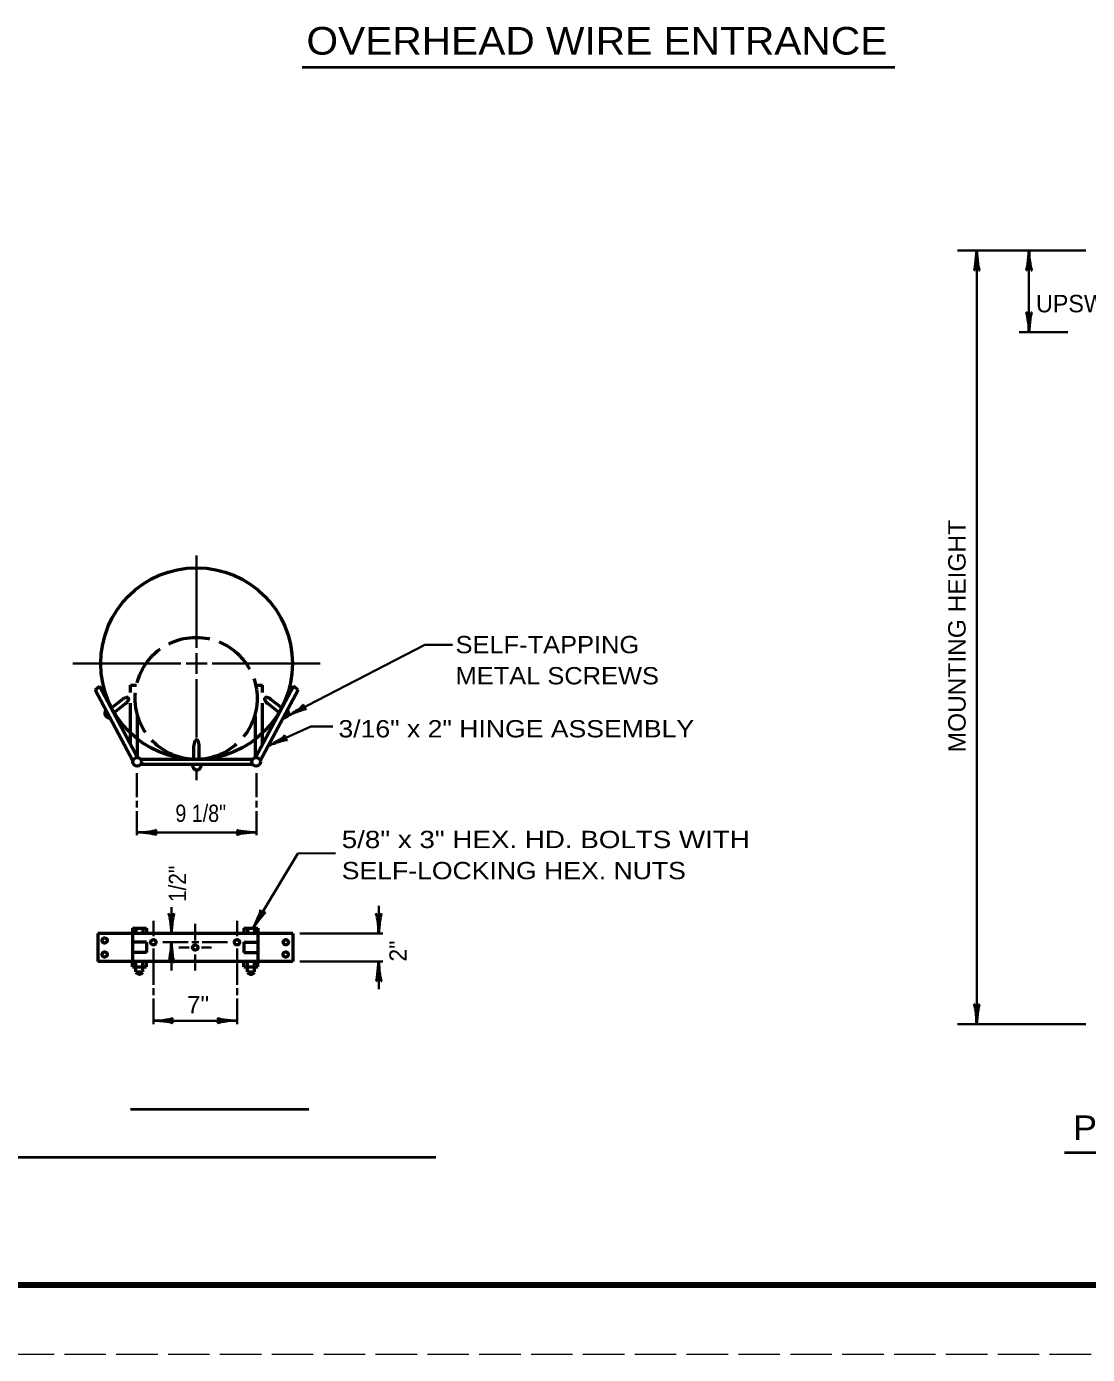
# Model space of a CAD drawing. Extents: x -1 to 679, y -228 to 440.
# Drawn here: x 202.5 to 356, y 0.2 to 192.2 of the extents above; entities that cross this region are included whole.
import ezdxf

# ---------------------------------------------------------------- set-up
doc = ezdxf.new("R2010")
doc.units = 0
doc.linetypes.add('LONG_DASHED', pattern=[7.5, 6, -1.5])
doc.layers.add('1', color=7, linetype='Continuous', lineweight=35)
doc.layers.add('61', color=7, linetype='Continuous', lineweight=35)

msp = doc.modelspace()

# ---------------------------------------------------------------- linework, layer by layer
at = {"layer": '1', "lineweight": 40}
for p, q in [((242.425, 186.371), (328.129, 186.371)), ((217.592, 35.681), (243.388, 35.681)), ((352.69, 29.414), (407.27, 29.414)), ((198.293, 28.717), (261.764, 28.717))]:
    msp.add_line(p, q, dxfattribs=at)
at = {"layer": '1'}
for p, q in [((355.77, 159.854), (337.171, 159.854)), ((339.971, 159.854), (339.971, 47.974)), ((347.53, 148.054), (347.53, 159.854)), ((353.171, 148.054), (346.13, 148.054)), ((227.134, 115.748), (227.134, 102.388)), ((240.289, 92.534), (260.144, 102.807)), ((260.144, 102.807), (264.151, 102.824)), ((209.234, 100.127), (224.874, 100.127)), ((225.614, 100.127), (228.654, 100.127)), ((227.134, 101.627), (227.134, 98.608)), ((229.394, 100.127), (245.014, 100.127)), ((227.134, 97.847), (227.134, 89.407)), ((218.511, 84.285), (218.511, 80.785)), ((227.134, 84.487), (227.134, 83.227)), ((235.796, 84.285), (235.796, 80.785)), ((218.511, 80.285), (218.511, 79.285)), ((218.511, 78.785), (218.511, 75.285)), ((235.796, 80.285), (235.796, 79.285)), ((235.796, 78.785), (235.796, 75.285)), ((218.511, 75.692), (235.796, 75.692)), ((235.269, 61.828), (241.758, 72.646)), ((241.758, 72.646), (247.232, 72.707)), ((223.503, 61.067), (223.503, 64.886)), ((253.482, 61.067), (253.482, 65.067)), ((220.894, 62.907), (220.894, 60.688)), ((226.934, 62.468), (226.934, 60.067)), ((232.994, 62.907), (232.994, 60.688)), ((222.274, 59.807), (225.934, 59.807)), ((223.503, 55.707), (223.503, 59.807)), ((226.434, 59.807), (227.454, 59.807)), ((227.954, 59.807), (231.594, 59.807)), ((242.054, 61.067), (254.054, 61.067)), ((220.894, 58.927), (220.894, 53.669)), ((224.554, 59.067), (226.074, 59.067)), ((226.934, 58.047), (226.934, 55.707)), ((227.834, 59.067), (229.294, 59.067)), ((232.994, 58.927), (232.994, 53.669)), ((242.054, 57.047), (254.054, 57.047)), ((253.482, 53.047), (253.482, 57.047)), ((220.894, 53.169), (220.894, 52.169)), ((232.994, 53.169), (232.994, 52.169)), ((220.894, 51.669), (220.894, 47.968)), ((232.994, 51.669), (232.994, 47.968)), ((220.894, 48.468), (232.994, 48.468)), ((355.77, 47.974), (337.171, 47.974))]:
    msp.add_line(p, q, dxfattribs=at)
at = {"layer": '1', "lineweight": 53}
for p, q in [((212.474, 96.328), (213.114, 96.847)), ((212.474, 96.328), (217.934, 86.067)), ((213.114, 96.847), (218.614, 86.507)), ((241.174, 96.847), (235.674, 86.528)), ((241.814, 96.328), (236.354, 86.067)), ((241.814, 96.328), (241.174, 96.847)), ((235.254, 85.507), (219.014, 85.507)), ((235.234, 86.248), (219.054, 86.248)), ((217.874, 61.828), (219.894, 61.828)), ((218.374, 61.828), (218.374, 61.067)), ((219.374, 61.828), (219.374, 61.067)), ((219.894, 61.828), (219.894, 61.067)), ((233.994, 61.828), (233.994, 61.067)), ((233.994, 61.828), (236.014, 61.828)), ((234.494, 61.828), (234.494, 61.067)), ((235.514, 61.828), (235.514, 61.067)), ((241.054, 61.067), (212.834, 61.067)), ((212.834, 61.067), (212.834, 57.047)), ((219.894, 59.807), (217.874, 59.807)), ((219.894, 59.807), (219.894, 58.307)), ((233.994, 59.807), (233.994, 58.307)), ((233.994, 59.807), (236.014, 59.807)), ((241.054, 61.067), (241.054, 57.047)), ((219.894, 58.307), (217.874, 58.307)), ((233.994, 58.307), (236.014, 58.307)), ((241.054, 57.047), (212.834, 57.047)), ((217.874, 56.247), (217.874, 57.008)), ((217.874, 56.247), (219.894, 56.247)), ((218.374, 55.508), (218.374, 57.008)), ((219.374, 55.508), (219.374, 57.008)), ((219.894, 56.247), (219.894, 57.008)), ((233.994, 56.247), (233.994, 57.008)), ((233.994, 56.247), (236.014, 56.247)), ((234.494, 55.508), (234.494, 57.008)), ((235.514, 55.508), (235.514, 57.008)), ((236.014, 56.247), (236.014, 57.008)), ((218.374, 55.508), (219.374, 55.508)), ((234.494, 55.508), (235.514, 55.508))]:
    msp.add_line(p, q, dxfattribs=at)
at = {"layer": '1', "linetype": 'LONG_DASHED', "lineweight": 53}
for p, q in [((217.594, 88.407), (217.594, 96.987)), ((217.594, 96.987), (218.454, 96.987)), ((235.674, 96.987), (236.694, 96.987)), ((236.694, 88.407), (236.694, 96.987)), ((214.794, 93.667), (216.394, 94.907)), ((215.154, 92.987), (216.854, 94.328)), ((239.114, 92.987), (237.434, 94.328)), ((239.494, 93.667), (237.894, 94.907)), ((218.614, 86.507), (218.614, 92.587)), ((235.674, 86.528), (235.674, 93.168)), ((226.754, 86.248), (226.754, 88.227)), ((227.514, 86.248), (227.514, 88.227))]:
    msp.add_line(p, q, dxfattribs=at)
at = {"layer": '1'}
msp.add_lwpolyline([(237.498, 88.217), (243.677, 90.992), (246.865, 90.992)], dxfattribs=at)
at = {"layer": '1', "lineweight": 53}
for points in [[(217.874, 61.828), (217.874, 61.067), (217.874, 57.047)], [(236.014, 61.828), (236.014, 61.067), (236.014, 57.047)]]:
    msp.add_lwpolyline(points, dxfattribs=at)
for centre, radius in [((227.133, 100.114), 13.86), ((218.531, 85.891), 0.63), ((235.74, 85.891), 0.63), ((213.837, 60.067), 0.378), ((220.888, 59.806), 0.378), ((232.984, 59.806), 0.378), ((240.055, 59.806), 0.378), ((213.837, 58.049), 0.378), ((226.948, 59.048), 0.378), ((240.029, 58.037), 0.378)]:
    msp.add_circle(centre, radius, dxfattribs=at)
at = {"layer": '1', "linetype": 'LONG_DASHED', "lineweight": 53}
msp.add_circle((227.068, 95.077), 8.82, dxfattribs=at)
at = {"layer": '1', "lineweight": 53}
for centre, radius, start, end in [((214.544, 92.942), 0.681, 138.1398, 277.864), ((239.754, 92.956), 0.681, 262.136, 41.8602), ((227.183, 85.365), 0.63, 167.65166, 11.75169), ((218.877, 55.792), 0.582, 209.9862, 330.0138), ((235.005, 55.756), 0.565, 206.79037, 333.20963)]:
    msp.add_arc(centre, radius, start, end, dxfattribs=at)
at = {"layer": '1', "lineweight": 40}
for centre, major_axis, ratio, start_param, end_param in [((339.766, 158.731), (0.177, 1.77), 0.07063, 3.1407148, 5.41811), ((340.258, 158.761), (-0.157, 1.8), 0.122415, 0.8963533, 3.1415927), ((347.327, 158.731), (0.177, 1.77), 0.07063, 3.1407148, 5.41811), ((347.818, 158.761), (-0.157, 1.8), 0.122415, 0.8963533, 3.1415927), ((347.261, 149.148), (0.157, -1.8), 0.122415, 0.8963533, 3.1415927), ((347.753, 149.178), (-0.177, -1.77), 0.07063, 3.1407148, 5.41811), ((241.131, 93.281), (-1.514, -0.959), 0.122415, 0.8963533, 3.1415927), ((241.131, 93.281), (-1.514, -0.959), 0.122415, 0.8963533, 3.1415927), ((241.381, 92.861), (1.641, 0.651), 0.07063, 6.2823074, 8.5597026), ((241.381, 92.861), (1.641, 0.651), 0.07063, 6.2823074, 8.5597026), ((238.38, 88.916), (-1.565, -0.874), 0.122415, 0.8963533, 3.1415927), ((238.607, 88.483), (-1.674, -0.559), 0.07063, 3.1407148, 5.41811), ((219.631, 75.481), (-1.756, 0.176), 0.07063, 3.1407148, 5.41811), ((219.631, 75.481), (-1.756, 0.176), 0.07063, 3.1407148, 5.41811), ((219.602, 75.969), (-1.786, -0.156), 0.122415, 0.8963533, 3.1415927), ((219.602, 75.969), (-1.786, -0.156), 0.122415, 0.8963533, 3.1415927), ((234.705, 75.416), (1.786, 0.156), 0.122415, 0.8963533, 3.1415927), ((234.705, 75.416), (1.786, 0.156), 0.122415, 0.8963533, 3.1415927), ((234.675, 75.904), (1.756, -0.176), 0.07063, 3.1407148, 5.41811), ((234.675, 75.904), (1.756, -0.176), 0.07063, 3.1407148, 5.41811), ((223.227, 62.159), (0.156, -1.786), 0.122415, 0.8963533, 3.1415927), ((223.227, 62.159), (0.156, -1.786), 0.122415, 0.8963533, 3.1415927), ((223.715, 62.188), (-0.176, -1.756), 0.07063, 3.1407148, 5.41811), ((223.715, 62.188), (-0.176, -1.756), 0.07063, 3.1407148, 5.41811), ((235.593, 62.905), (-0.785, -1.612), 0.122415, 0.8963533, 3.1415927), ((236.027, 62.68), (1.054, 1.416), 0.07063, 6.2823074, 8.5597026), ((253.205, 62.159), (0.156, -1.786), 0.122415, 0.8963533, 3.1415927), ((253.205, 62.159), (0.156, -1.786), 0.122415, 0.8963533, 3.1415927), ((253.693, 62.188), (-0.176, -1.756), 0.07063, 3.1407148, 5.41811), ((253.693, 62.188), (-0.176, -1.756), 0.07063, 3.1407148, 5.41811), ((223.292, 58.687), (0.176, 1.756), 0.07063, 3.1407148, 5.41811), ((223.292, 58.687), (0.176, 1.756), 0.07063, 3.1407148, 5.41811), ((223.779, 58.716), (-0.156, 1.786), 0.122415, 0.8963533, 3.1415927), ((223.779, 58.716), (-0.156, 1.786), 0.122415, 0.8963533, 3.1415927), ((253.27, 55.927), (0.176, 1.756), 0.07063, 3.1407148, 5.41811), ((253.27, 55.927), (0.176, 1.756), 0.07063, 3.1407148, 5.41811), ((253.758, 55.956), (-0.156, 1.786), 0.122415, 0.8963533, 3.1415927), ((253.758, 55.956), (-0.156, 1.786), 0.122415, 0.8963533, 3.1415927), ((339.701, 49.073), (0.157, -1.8), 0.122415, 0.8963533, 3.1415927), ((340.193, 49.102), (-0.177, -1.77), 0.07063, 3.1407148, 5.41811), ((221.985, 48.744), (-1.786, -0.156), 0.122415, 0.8963533, 3.1415927), ((221.985, 48.744), (-1.786, -0.156), 0.122415, 0.8963533, 3.1415927), ((222.015, 48.257), (-1.756, 0.176), 0.07063, 3.1407148, 5.41811), ((222.015, 48.257), (-1.756, 0.176), 0.07063, 3.1407148, 5.41811), ((231.903, 48.192), (1.786, 0.156), 0.122415, 0.8963533, 3.1415927), ((231.873, 48.68), (1.756, -0.176), 0.07063, 3.1407148, 5.41811)]:
    msp.add_ellipse(centre, major_axis=major_axis, ratio=ratio, start_param=start_param, end_param=end_param, dxfattribs=at)
at = {"layer": '1', "linetype": 'LONG_DASHED', "lineweight": 53}
for centre, major_axis, start_param, end_param in [((216.623, 94.618), (0.664, 0.518), 4.712389, 7.8539816), ((237.663, 94.618), (0.664, -0.518), 1.5707963, 4.712389), ((227.13, 88.236), (0.003, -0.842), 1.5707963, 4.712389)]:
    msp.add_ellipse(centre, major_axis=major_axis, ratio=0.448678, start_param=start_param, end_param=end_param, dxfattribs=at)
at = {"layer": '61', "lineweight": 158}
msp.add_line((668.081, 10.197), (29.021, 10.217), dxfattribs=at)
at = {"layer": '61', "linetype": 'LONG_DASHED', "lineweight": 13}
msp.add_line((679.021, 0.217), (-1.039, 0.197), dxfattribs=at)

# ---------------------------------------------------------------- texts
at = {"layer": '1'}
for s, height, width, p in [('OVERHEAD WIRE ENTRANCE', 4, 1.1, (243.028, 188.18)), ('SELF-TAPPING', 2.5, 1.1, (264.593, 101.604)), ('METAL SCREWS', 2.5, 1.1, (264.593, 97.104)), ('3/16" x 2" HINGE ASSEMBLY', 2.5, 1.15, (247.652, 89.434)), ('9 1/8"', 2.5, 0.85, (224.073, 77.212)), ('5/8" x 3" HEX. HD. BOLTS WITH', 2.5, 1.2, (248.132, 73.425)), ('SELF-LOCKING HEX. NUTS', 2.5, 1.15, (248.132, 68.925)), ('7"', 2.5, 1.05, (225.745, 49.541)), ('POLE COMPONENTS', 3.528, 1.1, (353.911, 31.234))]:
    msp.add_text(s, height=height, dxfattribs=dict(at, width=width)).set_placement(p)
msp.add_text('UPSWEEP', height=2.52, dxfattribs=at).set_placement((348.55, 150.914))
for s, height, width, p in [('MOUNTING HEIGHT', 2.52, 1.05, (338.37, 87.274)), ('1/2"', 2.5, 0.9, (225.617, 65.629))]:
    msp.add_text(s, height=height, rotation=90, dxfattribs=dict(at, width=width)).set_placement(p)
msp.add_text('2"', height=2.5, rotation=90, dxfattribs=at).set_placement((257.525, 57.005))

doc.saveas('drawing.dxf')
